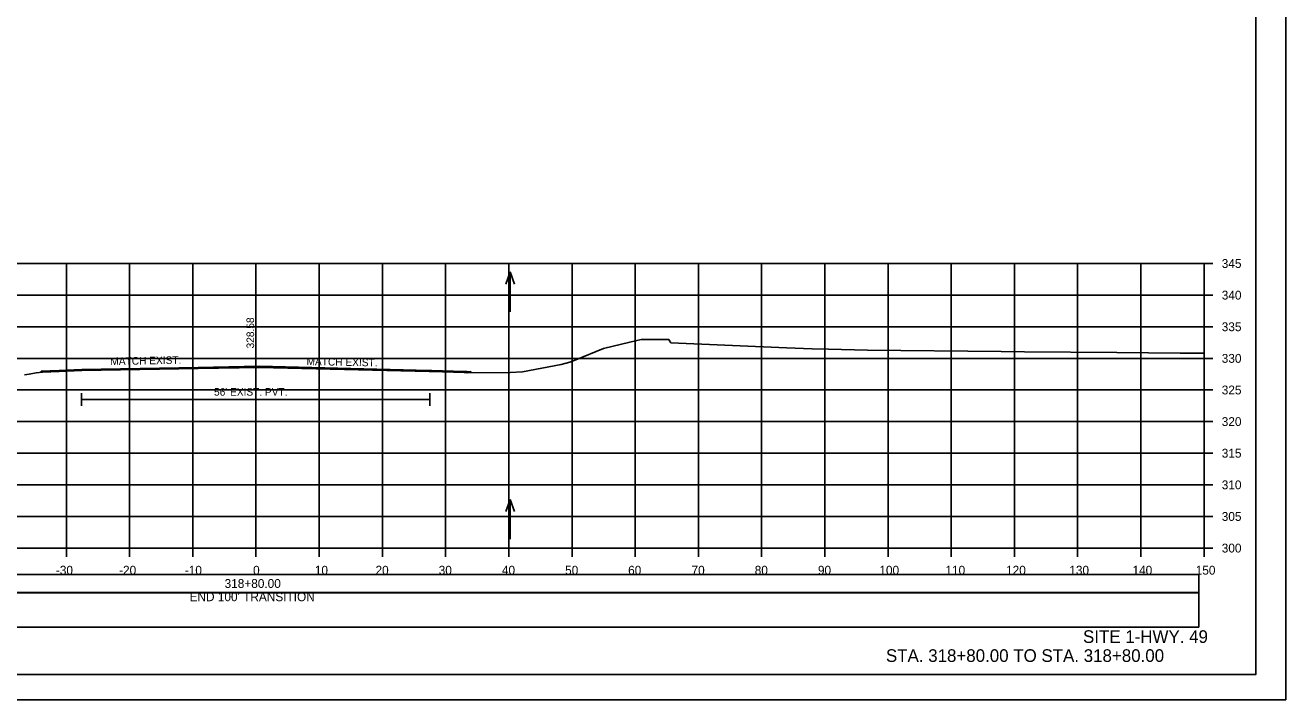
# Model space of a CAD drawing. Extents: x 1368122 to 1710785, y 373130 to 557566.
# Drawn here: x 1369319 to 1369518.5, y 375690.4 to 375797.1 of the extents above; entities that cross this region are included whole.
import ezdxf

# ---------------------------------------------------------------- set-up
doc = ezdxf.new("R2010")
doc.units = 0
for name, color, linetype in [('R_Alt Surface', 7, 'Continuous'), ('R_Axis', 7, 'Continuous'), ('R_Axis Annot', 7, 'Continuous'), ('R_Border', 7, 'Continuous'), ('R_Draft', 7, 'Continuous'), ('R_Exist Surface', 7, 'Continuous'), ('R_Fin Surface', 7, 'Continuous'), ('R_Grid', 7, 'Continuous'), ('R_No Plot', 7, 'Continuous'), ('R_Water', 7, 'Continuous'), ('R_Water Annot', 7, 'Continuous'), ('R_Xsect Elev', 7, 'Continuous'), ('R_Xsect Slope', 7, 'Continuous')]:
    doc.layers.add(name, color=color, linetype=linetype)

msp = doc.modelspace()

# ---------------------------------------------------------------- linework, layer by layer
for points in [[(1369206.41, 375707.36), (1369504.71, 375707.36), (1369504.71, 375710.17), (1369206.41, 375710.17)], [(1369206.41, 375701.89), (1369504.71, 375701.89), (1369504.71, 375707.3), (1369206.41, 375707.3)]]:
    msp.add_lwpolyline(points, close=True)
at = {"layer": 'R_Alt Surface'}
for points in [[(1369327.95, 375738.87), (1369327.95, 375736.87)], [(1369327.95, 375737.87), (1369383.05, 375737.87)], [(1369383.05, 375738.87), (1369383.05, 375736.87)]]:
    msp.add_lwpolyline(points, dxfattribs=at)
at = {"layer": 'R_Axis'}
for p, q in [((1369505.56, 375714.37), (1369505.56, 375759.37)), ((1369506.96, 375759.37), (1369505.56, 375759.37)), ((1369506.96, 375754.37), (1369505.56, 375754.37)), ((1369506.96, 375749.37), (1369505.56, 375749.37)), ((1369506.96, 375744.37), (1369505.56, 375744.37)), ((1369506.96, 375739.37), (1369505.56, 375739.37)), ((1369506.96, 375734.37), (1369505.56, 375734.37)), ((1369506.96, 375729.37), (1369505.56, 375729.37)), ((1369506.96, 375724.37), (1369505.56, 375724.37)), ((1369506.96, 375719.37), (1369505.56, 375719.37)), ((1369205.56, 375714.37), (1369505.56, 375714.37)), ((1369325.56, 375712.97), (1369325.56, 375714.37)), ((1369335.56, 375712.97), (1369335.56, 375714.37)), ((1369345.56, 375712.97), (1369345.56, 375714.37)), ((1369355.56, 375712.97), (1369355.56, 375714.37)), ((1369365.56, 375712.97), (1369365.56, 375714.37)), ((1369375.56, 375712.97), (1369375.56, 375714.37)), ((1369385.56, 375712.97), (1369385.56, 375714.37)), ((1369395.56, 375712.97), (1369395.56, 375714.37)), ((1369405.56, 375712.97), (1369405.56, 375714.37)), ((1369415.56, 375712.97), (1369415.56, 375714.37)), ((1369425.56, 375712.97), (1369425.56, 375714.37)), ((1369435.56, 375712.97), (1369435.56, 375714.37)), ((1369445.56, 375712.97), (1369445.56, 375714.37)), ((1369455.56, 375712.97), (1369455.56, 375714.37)), ((1369465.56, 375712.97), (1369465.56, 375714.37)), ((1369475.56, 375712.97), (1369475.56, 375714.37)), ((1369485.56, 375712.97), (1369485.56, 375714.37)), ((1369495.56, 375712.97), (1369495.56, 375714.37)), ((1369505.56, 375712.97), (1369505.56, 375714.37)), ((1369506.96, 375714.37), (1369505.56, 375714.37))]:
    msp.add_line(p, q, dxfattribs=at)
at = {"layer": 'R_Border'}
for q in [(1369513.74, 375899.83), (1369197.56, 375694.37)]:
    msp.add_line((1369513.74, 375694.37), q, dxfattribs=at)
at = {"layer": 'R_Exist Surface'}
msp.add_lwpolyline([(1369318.95, 375741.78), (1369319.65, 375741.86), (1369320.78, 375742.07), (1369321.79, 375742.21), (1369324.42, 375742.3), (1369328.02, 375742.45), (1369346.42, 375742.77), (1369356.14, 375742.95), (1369382.94, 375742.3), (1369383.33, 375742.29), (1369383.39, 375742.28), (1369388.5, 375742.11), (1369388.94, 375742.1), (1369388.95, 375742.09), (1369388.97, 375742.09), (1369395.77, 375742.16), (1369397.71, 375742.25), (1369403.85, 375743.4), (1369405.22, 375743.78), (1369406.17, 375744.15), (1369410.56, 375745.93), (1369414.73, 375746.94), (1369416.5, 375747.34), (1369417.23, 375747.34), (1369420.45, 375747.34), (1369420.49, 375747.34), (1369420.5, 375747.34), (1369420.57, 375747.34), (1369420.9, 375747.34), (1369420.95, 375747.24), (1369421.2, 375746.84), (1369439.5, 375746.06), (1369443.58, 375745.89), (1369446.15, 375745.85), (1369452.32, 375745.69), (1369473.47, 375745.43), (1369477.14, 375745.39), (1369491.76, 375745.29), (1369501.8, 375745.21), (1369502.93, 375745.21), (1369504.04, 375745.2), (1369505.56, 375745.2)], dxfattribs=at)
at = {"layer": 'R_Fin Surface'}
for p, q in [((1369321.56, 375742.17), (1369321.56, 375742.37)), ((1369389.56, 375742.1), (1369389.56, 375742.27))]:
    msp.add_line(p, q, dxfattribs=at)
msp.add_lwpolyline([(1369321.56, 375742.37), (1369324.41, 375742.47), (1369328.01, 375742.62), (1369346.42, 375742.94), (1369356.14, 375743.12), (1369382.95, 375742.47), (1369383.34, 375742.46), (1369383.39, 375742.45), (1369388.5, 375742.28), (1369388.95, 375742.27), (1369388.96, 375742.26), (1369388.97, 375742.26), (1369389.56, 375742.27)], dxfattribs=at)
at = {"layer": 'R_Grid'}
for p, q in [((1369205.56, 375759.37), (1369505.56, 375759.37)), ((1369325.56, 375714.37), (1369325.56, 375759.37)), ((1369335.56, 375714.37), (1369335.56, 375759.37)), ((1369345.56, 375714.37), (1369345.56, 375759.37)), ((1369355.56, 375714.37), (1369355.56, 375759.37)), ((1369365.56, 375714.37), (1369365.56, 375759.37)), ((1369375.56, 375714.37), (1369375.56, 375759.37)), ((1369385.56, 375714.37), (1369385.56, 375759.37)), ((1369395.56, 375714.37), (1369395.56, 375759.37)), ((1369405.56, 375714.37), (1369405.56, 375759.37)), ((1369415.56, 375714.37), (1369415.56, 375759.37)), ((1369425.56, 375714.37), (1369425.56, 375759.37)), ((1369435.56, 375714.37), (1369435.56, 375759.37)), ((1369445.56, 375714.37), (1369445.56, 375759.37)), ((1369455.56, 375714.37), (1369455.56, 375759.37)), ((1369465.56, 375714.37), (1369465.56, 375759.37)), ((1369475.56, 375714.37), (1369475.56, 375759.37)), ((1369485.56, 375714.37), (1369485.56, 375759.37)), ((1369495.56, 375714.37), (1369495.56, 375759.37)), ((1369505.56, 375714.37), (1369505.56, 375759.37)), ((1369205.56, 375754.37), (1369505.56, 375754.37)), ((1369205.56, 375749.37), (1369505.56, 375749.37)), ((1369205.56, 375744.37), (1369505.56, 375744.37)), ((1369205.56, 375739.37), (1369505.56, 375739.37)), ((1369205.56, 375734.37), (1369505.56, 375734.37)), ((1369205.56, 375729.37), (1369505.56, 375729.37)), ((1369205.56, 375724.37), (1369505.56, 375724.37)), ((1369205.56, 375719.37), (1369505.56, 375719.37)), ((1369205.56, 375714.37), (1369505.56, 375714.37))]:
    msp.add_line(p, q, dxfattribs=at)
at = {"layer": 'R_No Plot'}
msp.add_line((1369185.16, 375690.39), (1369518.49, 375690.39), dxfattribs=at)
for points in [[(1369185.15, 375903.72), (1369518.49, 375903.72), (1369518.49, 375690.38), (1369185.15, 375690.38)], [(1369431.48, 375899.83), (1369451.1, 375899.83), (1369451.1, 375889.95), (1369467.21, 375889.95), (1369490.41, 375889.95), (1369490.53, 375861.79), (1369513.74, 375861.79), (1369513.74, 375694.37), (1369197.56, 375694.37), (1369197.56, 375899.83)]]:
    msp.add_lwpolyline(points, close=True, dxfattribs=at)
at = {"layer": 'R_Water Annot'}
for p, q in [((1369395.77, 375758.03), (1369395.07, 375756.11)), ((1369395.77, 375751.75), (1369395.77, 375758.03)), ((1369395.77, 375758.03), (1369396.47, 375756.11)), ((1369395.77, 375722.06), (1369395.07, 375720.13)), ((1369395.77, 375715.77), (1369395.77, 375722.06)), ((1369395.77, 375722.06), (1369396.47, 375720.13))]:
    msp.add_line(p, q, dxfattribs=at)
at = {"layer": 'R_Xsect Elev'}
msp.add_line((1369355.56, 375742.94), (1369355.56, 375752.94), dxfattribs=at)

# ---------------------------------------------------------------- texts
at = {"layer": 'R_Axis Annot'}
for s, p in [('345', (1369508.36, 375758.67)), ('340', (1369508.36, 375753.67)), ('335', (1369508.36, 375748.67)), ('330', (1369508.36, 375743.67)), ('325', (1369508.36, 375738.67)), ('320', (1369508.36, 375733.67)), ('315', (1369508.36, 375728.67)), ('310', (1369508.36, 375723.67)), ('305', (1369508.36, 375718.67)), ('300', (1369508.36, 375713.67)), ('-30', (1369323.9, 375710.17)), ('-20', (1369333.9, 375710.17)), ('-10', (1369344.3, 375710.17)), ('0', (1369355.1, 375710.17)), ('10', (1369364.87, 375710.17)), ('20', (1369374.47, 375710.17)), ('30', (1369384.47, 375710.17)), ('40', (1369394.47, 375710.17)), ('50', (1369404.47, 375710.17)), ('60', (1369414.44, 375710.17)), ('70', (1369424.47, 375710.17)), ('80', (1369434.47, 375710.17)), ('90', (1369444.47, 375710.17)), ('100', (1369454.19, 375710.17)), ('110', (1369464.64, 375710.17)), ('120', (1369474.24, 375710.17)), ('130', (1369484.24, 375710.17)), ('140', (1369494.24, 375710.17)), ('150', (1369504.24, 375710.17)), ('318+80.00', (1369350.59, 375708.07)), ("END 100' TRANSITION", (1369345.05, 375705.97))]:
    msp.add_text(s, height=1.4, dxfattribs=at).set_placement(p)
at = {"layer": 'R_Draft'}
for s, p in [('SITE 1-HWY. 49', (1369486.41, 375699.37)), ('STA. 318+80.00 TO STA. 318+80.00', (1369455.23, 375696.37))]:
    msp.add_text(s, height=2, dxfattribs=at).set_placement(p)
at = {"layer": 'R_Water'}
msp.add_text("56' EXIST. PVT.", height=1.2, dxfattribs=at).set_placement((1369348.92, 375738.47))
at = {"layer": 'R_Xsect Elev'}
msp.add_text('328.58', height=1.2, rotation=90, dxfattribs=at).set_placement((1369355.26, 375745.94))
at = {"layer": 'R_Xsect Slope'}
for rotation, p in [(1.1458, (1369332.53, 375743.3)), (358.8542, (1369363.55, 375743.31))]:
    msp.add_text('MATCH EXIST.', height=1.2, rotation=rotation, dxfattribs=at).set_placement(p)

doc.saveas('drawing.dxf')
